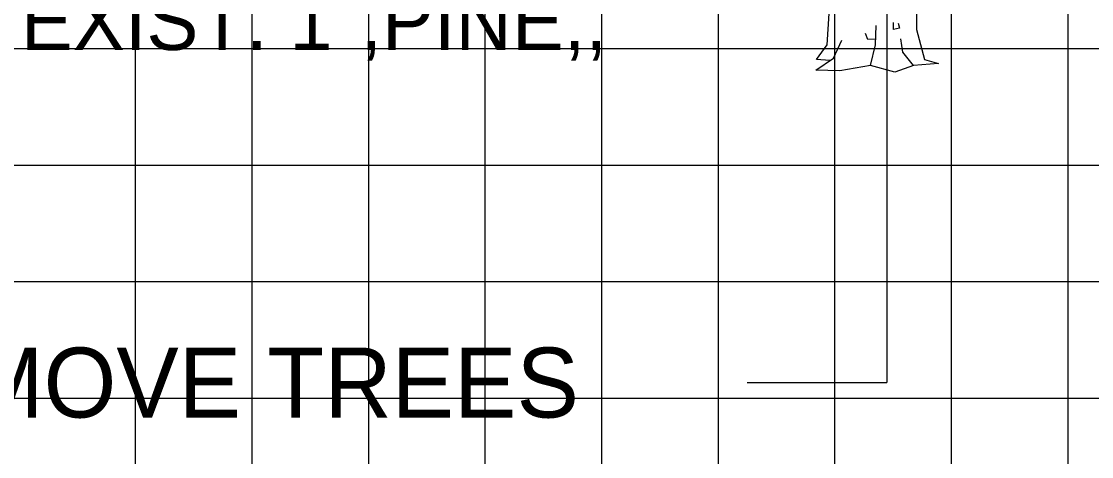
# Model space of a CAD drawing. Extents: x 1146525 to 1146695, y 608981 to 609091.
# Drawn here: x 1146566.69 to 1146575.87, y 608992.83 to 608996.57 of the extents above; entities that cross this region are included whole.
import ezdxf

# ---------------------------------------------------------------- set-up
doc = ezdxf.new("R2010")
doc.units = 0
for name, color, linetype in [('ANNOTATION', 7, 'Continuous'), ('D_Text_Monospaced', 7, 'Continuous'), ('MAJOR', 7, 'Continuous'), ('MINOR', 7, 'Continuous'), ('S_Trees_Conifer_NonPay', 7, 'Continuous')]:
    doc.layers.add(name, color=color, linetype=linetype)

msp = doc.modelspace()

# ---------------------------------------------------------------- linework, layer by layer
at = {"layer": 'ANNOTATION'}
for p in [(1146574.1168, 608998.031), (1146572.9168, 608993.4689)]:
    msp.add_line(p, (1146574.1168, 608993.4689), dxfattribs=at)
at = {"layer": 'MAJOR'}
for p, q in [((1146567.6713, 608990.3351), (1146567.6713, 609010.3351)), ((1146572.6713, 608990.3351), (1146572.6713, 609010.3351)), ((1146537.6713, 608995.3351), (1146677.6713, 608995.3351))]:
    msp.add_line(p, q, dxfattribs=at)
at = {"layer": 'MINOR'}
for p, q in [((1146568.6713, 608990.3351), (1146568.6713, 609010.3351)), ((1146569.6713, 608990.3351), (1146569.6713, 609010.3351)), ((1146570.6713, 608990.3351), (1146570.6713, 609010.3351)), ((1146571.6713, 608990.3351), (1146571.6713, 609010.3351)), ((1146573.6713, 608990.3351), (1146573.6713, 609010.3351)), ((1146574.6713, 608990.3351), (1146574.6713, 609010.3351)), ((1146575.6713, 608990.3351), (1146575.6713, 609010.3351)), ((1146537.6713, 608996.3351), (1146677.6713, 608996.3351)), ((1146537.6713, 608994.3351), (1146677.6713, 608994.3351)), ((1146537.6713, 608993.3351), (1146677.6713, 608993.3351))]:
    msp.add_line(p, q, dxfattribs=at)
at = {"layer": 'S_Trees_Conifer_NonPay'}
for points in [[(1146573.6284, 608996.2318), (1146573.5123, 608996.241), (1146573.6041, 608996.3663), (1146573.6376, 608996.907), (1146573.6579, 608997.424), (1146573.6579, 608998.3433)], [(1146574.3712, 608998.2154), (1146574.3712, 608996.4975), (1146574.4407, 608996.241), (1146574.5602, 608996.2068), (1146574.3436, 608996.1904), (1146574.1842, 608996.132), (1146573.9749, 608996.1904), (1146573.7124, 608996.1432), (1146573.5064, 608996.1491), (1146573.6579, 608996.2521), (1146573.7294, 608996.4056)], [(1146573.9749, 608996.1904), (1146574.0195, 608996.3663), (1146574.0254, 608996.531)], [(1146574.2124, 608996.5533), (1146574.2235, 608996.5087), (1146574.173, 608996.4975), (1146574.173, 608996.5592)], [(1146574.0214, 608996.4161), (1146573.9519, 608996.4109), (1146573.9335, 608996.4634)], [(1146574.3436, 608996.1904), (1146574.2537, 608996.3026), (1146574.2367, 608996.4168)]]:
    msp.add_lwpolyline(points, dxfattribs=at)

# ---------------------------------------------------------------- texts
at = {"layer": 'ANNOTATION'}
msp.add_text('REMOVE TREES', height=0.599999, dxfattribs=at).set_placement((1146565.0991, 608993.1689))
at = {"layer": 'D_Text_Monospaced'}
msp.add_text('EXIST. 1",PINE,,', height=0.49998, dxfattribs=at).set_placement((1146566.6861, 608996.3223))

doc.saveas('drawing.dxf')
